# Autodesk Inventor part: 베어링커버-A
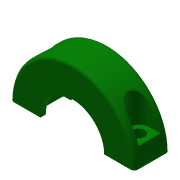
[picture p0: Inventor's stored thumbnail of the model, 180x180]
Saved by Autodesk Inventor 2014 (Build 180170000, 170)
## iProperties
Created: 2018-01
Part Number: 베어링커버-A
Material: Aluminum 6061
Document SubType Name: Modeling
Designer: mduedu
Density: 2.71 g/cm^3
Mass: 7.21302 g
Surface Area: 19.9383 cm^2
Volume: 2.66163 cm^3
Appearance: Dark Green
Author: mduedu
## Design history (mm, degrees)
sketch "스케치1"
  geometry: L1 (-17.5, 0)-(17.5, 0); A1 r 17.5 centre (0, 0) between (-17.5, 0) and (17.5, 0); 2 further points
  constraints: 2 coincident, 2 end point, 2 point on circle, 1 centre point, 1 horizontal, 1 midpoint
  dimensions: "d0" = 35 diameter of A1
extrude "돌출1" new body sketch "스케치1" stored distance "d1" = 10; taper "d2" = 0 deg
sketch "스케치2"
  geometry: C1 r 11 at (0, 0); C2 r 9 at (0, 0); 1 further point
  constraints: 2 centre point, 2 coincident
  dimensions: "d3" = 22 diameter of C1; "d4" = 18 diameter of C2
extrude "돌출2" cut sketch "스케치2" stored distance "d5" = 7; taper "d6" = 0 deg
extrude "돌출3" cut sketch "스케치2" stored distance "d7" = 7; taper "d8" = 0 deg
fillet "모깎기1" dims "d9" = 0.3
fillet "모깎기2" dims "d10" = 1
node "작업 평면1"
sketch "스케치3"
  geometry: L1 (-15.5, -3.5)-(33.5, -3.5) reference; L2 (-4.771, -6.5)-(-7.771, -6.5); L3 (-7.771, -6.5)-(-7.771, -0.5); L4 (-7.771, -0.5)-(-4.771, -0.5); L5 (-0.46, -7)-(1.517, -7) reference; L6 (1.517, -7)-(1.517, -8.5) reference; L7 (1.517, -8.5)-(-6.724, -8.5) reference; L8 (-7.771, -7.5)-(-7.771, 0.5) reference; L9 (-6.724, 1.5)-(1.517, 1.5) reference; L10 (1.517, 1.5)-(1.517, 0) reference; L11 (1.517, 0)-(-0.46, 0) reference; L12 (-0.798, -0.3)-(-0.798, -6.7) reference; L13 (18.798, -6.7)-(18.798, -0.3) reference; L14 (18.46, 0)-(16.483, 0) reference; L15 (16.483, 0)-(16.483, 1.5) reference; L16 (16.483, 1.5)-(24.724, 1.5) reference; L17 (25.771, 0.5)-(25.771, -7.5) reference; L18 (24.724, -8.5)-(16.483, -8.5) reference; L19 (16.483, -8.5)-(16.483, -7) reference; L20 (16.483, -7)-(18.46, -7) reference; A1 r 3 centre (-4.771, -3.5) between (-4.771, -6.5) and (-4.771, -0.5); 1 further point
  constraints: 6 end point, 2 point on circle, 2 tangent, 1 centre point, 1 collinear, 1 horizontal, 1 parallel, 1 perpendicular, 1 point on line, 8 other
  dimensions: "d12" = 6 distance between parallel lines of L4 L2; "d14" = 6 dimension on A1 L3
extrude "돌출4" cut sketch "스케치3" stored distance "d15" = 0; taper "d16" = 0 deg
sketch "스케치4"
  geometry: 7 further points
  constraints: 4 vertical alignment, 2 horizontal alignment
sketch "스케치5"
  geometry: 2 further points
  constraints: 2 other
hole "구멍1" sketch "스케치5" at (-22.771, 3.5), (4.771, 3.5) diameter "d17" = 3.4; stored, may be unused: countersink angle "d21" = 90 deg, drill point angle "d23" = 0 deg; dims "d18" = 6, "d19" = 4, "d20" = 2, "d22" = 8
fillet "모깎기3" dims "d24" = 0.1
node "솔리드1"
mirror "대칭1"
node "절단 모서리 투영1"
other parameters: "d11" = -5
